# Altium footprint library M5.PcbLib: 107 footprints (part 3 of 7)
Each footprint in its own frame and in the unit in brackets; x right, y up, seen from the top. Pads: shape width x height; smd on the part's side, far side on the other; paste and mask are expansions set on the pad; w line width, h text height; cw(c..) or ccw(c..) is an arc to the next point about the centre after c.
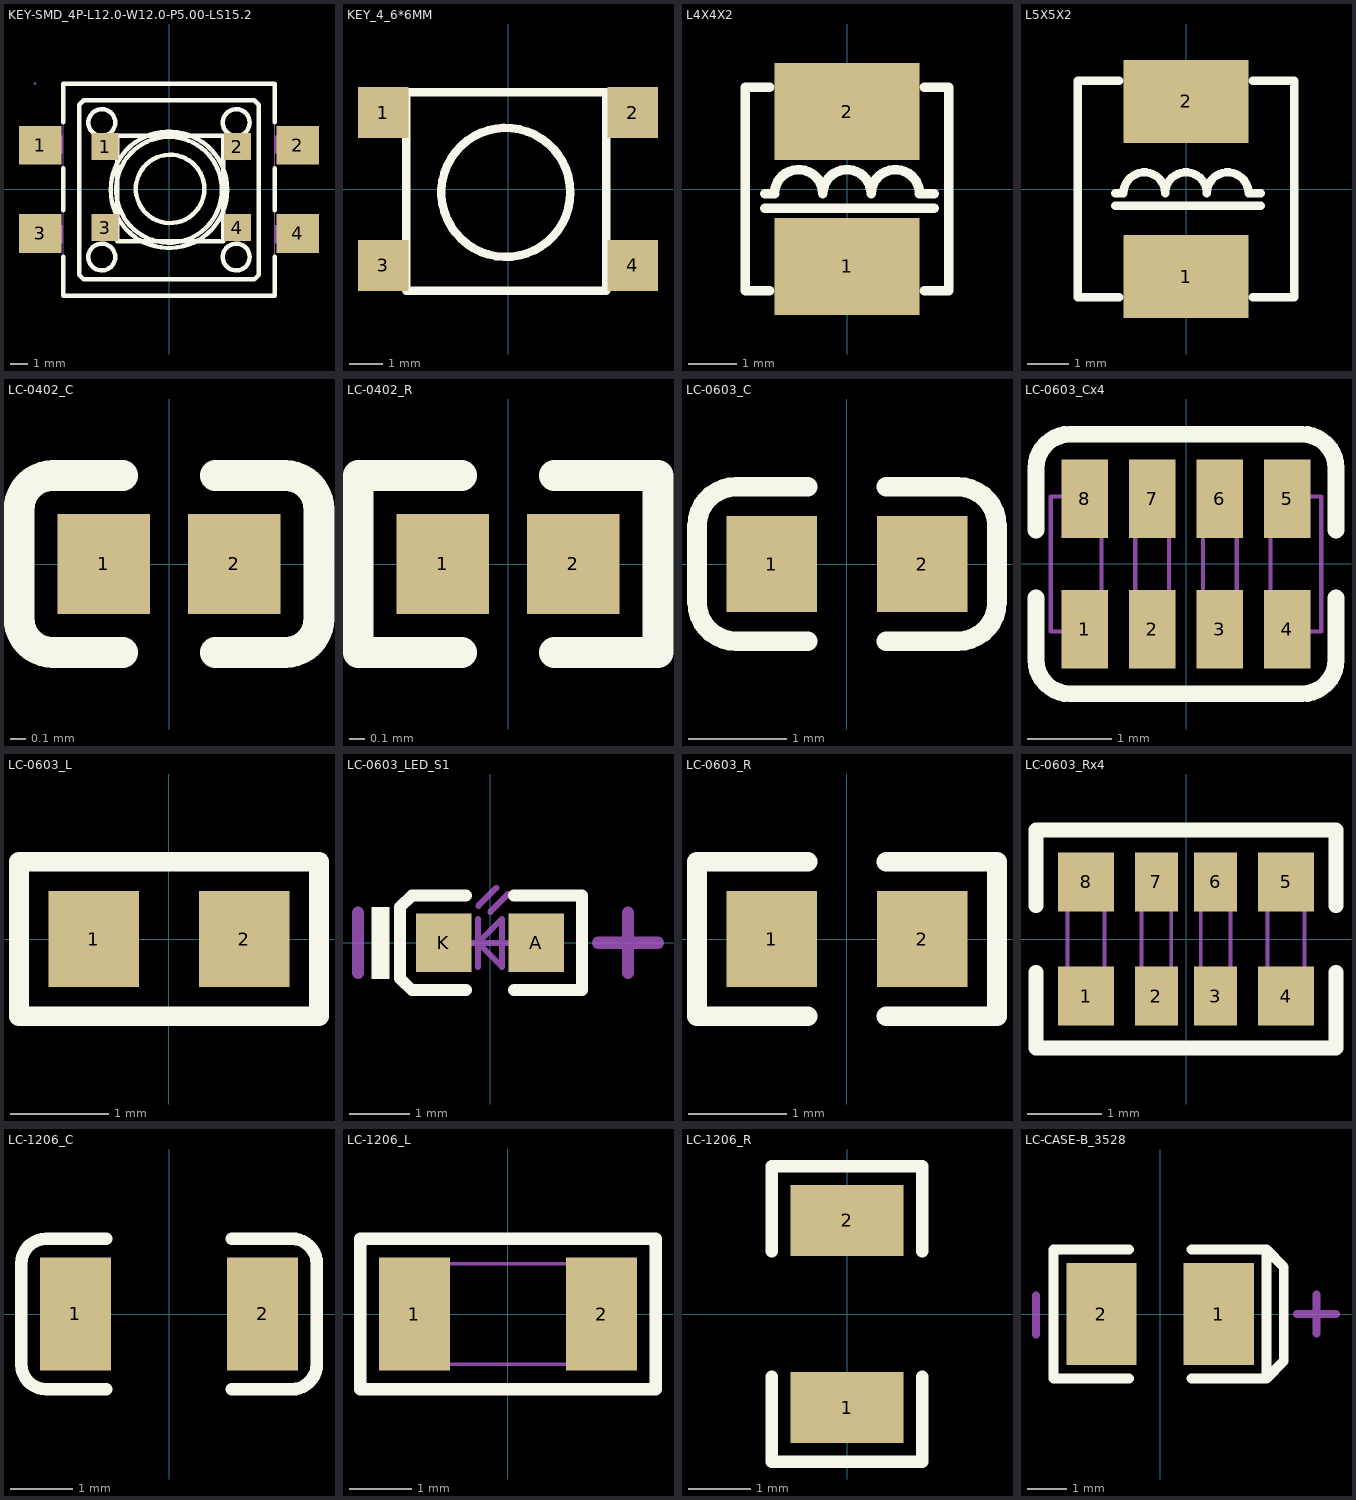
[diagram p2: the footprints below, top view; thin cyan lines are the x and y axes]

## KEY-SMD_4P-L12.0-W12.0-P5.00-LS15.2 [mil]
pads (8):
  rect 94.49x86.61 smd paste+0 mask+1.97: 1(-287.4,98.42) 2(287.4,98.42) 3(-287.4,-98.42) 4(287.4,-98.42)
  rect 60x60 smd: 1(-142.5,95.5) 2(152.5,95.5) 3(-142.5,-85.5) 4(152.5,-85.5)
Top Overlay:
  circle w10: c2.44,1.01 r76.32
  circle w10: c-150,149.03 r30
  circle w10: c150,149.03 r30
  circle w10: c-150,-150.97 r30
  circle w10: c150,-150.97 r30
  circle w10: c0,-0.97 r130
  circle w10: c0,-0.97 r118.11
  lines w10: -236.22,-149.93 -236.22,-237.19 236.22,-237.19 236.22,-149.93 ; -236.22,-46.92 -236.22,46.92 ; -236.22,149.93 -236.22,235.25 236.22,235.25 236.22,149.93 ; 236.22,-46.92 236.22,46.92 ; -200,-190.97 -190,-200.97 190,-200.97 200,-190.97 200,189.03 190,199.03 -190,199.03 -200,189.03 -200,-190.97 ; -115.22,-115.5 121,-115.5 121,119.5 -115.22,119.5 -115.22,-115.5
Mechanical 15:
  region: -296.65,236.22 -297.4,234.42 -299.21,233.67 -301.02,234.42 -301.77,236.22 -301.02,238.03 -299.21,238.78 -297.4,238.03
  region: 235.83,-119.68 235.83,-80.31 272.05,-80.31 272.05,-119.68
  region: 271.65,-119.68 271.65,-80.31 299.21,-80.31 299.21,-119.68
  region: -272.05,-119.68 -272.05,-80.31 -235.83,-80.31 -235.83,-119.68
  region: -299.21,-119.68 -299.21,-80.31 -271.65,-80.31 -271.65,-119.68
  region: 235.83,80.32 235.83,119.69 272.05,119.69 272.05,80.32
  region: 271.65,80.32 271.65,119.69 299.21,119.69 299.21,80.32
  region: -272.05,80.32 -272.05,119.69 -235.83,119.69 -235.83,80.32
  region: -299.21,80.32 -299.21,119.69 -271.65,119.69 -271.65,80.32
  lines w2: -236.22,-236.22 -236.22,236.22 236.22,236.22 236.22,-236.22 -236.22,-236.22
3D body: height 286.61, standoff -0.8, extent -164.29,-110.69 174.29,125.53
3D body: height 275.59, standoff 0, extent -420.06,-419.92 425.06,414.57

## KEY_4_6*6MM [mil]
pads (4):
  rect 60x60 smd: 1(-147.5,90.5) 2(147.5,90.5) 3(-147.5,-90.5) 4(147.5,-90.5)
Top Overlay:
  circle w10: c-2.56,-3.99 r76.32
  lines w10: -120.22,-120.5 116,-120.5 116,114.5 -120.22,114.5 -120.22,-120.5
3D body: height 286.61, standoff -0.8, extent -169.29,-115.69 169.29,120.53

## L4X4X2 [mm]
pads (2):
  rect 3x2 smd: 1(0,-1.6) 2(0,1.6)
Top Overlay:
  lines w0.2: -1.7,-0.4 1.8,-0.4 ; -1.7,-0.1 -1.5,-0.1 cw(c-1,-0.1) -0.5,-0.1 cw(c0,-0.1) 0.5,-0.1 cw(c1,-0.1) 1.5,-0.1 1.8,-0.1 ; -1.6,-2.1 -2.1,-2.1 -2.1,2.1 -1.6,2.1 ; 1.6,-2.1 2.1,-2.1 2.1,2.1 1.6,2.1
3D body: height 1.8, standoff -0.07, extent -2.03,-2.295 2.03,2.295

## L5X5X2 [mm]
pads (2):
  rect 3x2 smd: 1(0,-2.1) 2(0,2.1)
Top Overlay:
  lines w0.2: -1.7,-0.4 1.8,-0.4 ; -1.7,-0.1 -1.5,-0.1 cw(c-1,-0.1) -0.5,-0.1 cw(c0,-0.1) 0.5,-0.1 cw(c1,-0.1) 1.5,-0.1 1.8,-0.1 ; -1.6,-2.6 -2.6,-2.6 -2.6,2.6 -1.6,2.6 ; 1.6,-2.6 2.6,-2.6 2.6,2.6 1.6,2.6
3D body: height 1.9, standoff 0, extent -2.4,-2.4 2.4,2.4

## LC-0402_C [mm]
pads (2):
  rect 0.6x0.65 smd mask+0.051: 1(-0.425,0) 2(0.425,0)
Top Overlay:
  lines w0.2: -0.755,-0.575 cw(c-0.755,-0.355) -0.975,-0.355 -0.975,0.355 cw(c-0.755,0.355) -0.755,0.575 ; -0.75,-0.575 -0.3,-0.575 ; -0.75,0.575 -0.3,0.575 ; 0.3,-0.575 0.75,-0.575 ; 0.3,0.575 0.75,0.575 ; 0.755,-0.575 ccw(c0.755,-0.355) 0.975,-0.355 0.975,0.355 ccw(c0.755,0.355) 0.755,0.575
3D body: height 0.2, standoff 0, extent -0.483,-0.3 0.517,0.3

## LC-0402_R [mm]
pads (2):
  rect 0.6x0.65 smd mask+0.051: 1(-0.425,0) 2(0.425,0)
Top Overlay:
  lines w0.2: -0.3,-0.575 -0.975,-0.575 -0.975,0.575 -0.3,0.575 ; 0.3,-0.575 0.975,-0.575 0.975,0.575 0.3,0.575
3D body: height 0.41, standoff 0, extent -0.575,-0.275 0.575,0.275

## LC-0603_C [mm]
pads (2):
  rect 0.93x0.98 smd: 1(-0.77,0) 2(0.77,0)
Top Overlay:
  lines w0.2: -0.4,-0.79 -1.135,-0.79 cw(c-1.135,-0.39) -1.535,-0.39 -1.535,0.39 cw(c-1.135,0.39) -1.135,0.79 -0.4,0.79 ; 0.4,-0.79 1.135,-0.79 ccw(c1.135,-0.39) 1.535,-0.39 1.535,0.39 ccw(c1.135,0.39) 1.135,0.79 0.4,0.79
3D body: height 0.3, standoff 0, extent -0.8,-0.4 0.8,0.4

## LC-0603_Cx4 [mm]
pads (8):
  rect 0.55x0.93 smd mask+0.051: 1(-1.2,-0.77) 2(-0.4,-0.77) 3(0.4,-0.77) 4(1.2,-0.77) 5(1.2,0.77) 6(0.4,0.77) 7(-0.4,0.77) 8(-1.2,0.77)
Top Overlay:
  lines w0.2: -1.775,-0.4 -1.775,-1.135 ccw(c-1.375,-1.135) -1.375,-1.535 1.375,-1.535 ccw(c1.375,-1.135) 1.775,-1.135 1.775,-0.4 ; -1.775,0.4 -1.775,1.135 cw(c-1.375,1.135) -1.375,1.535 1.375,1.535 cw(c1.375,1.135) 1.775,1.135 1.775,0.4
Mechanical 13:
  lines w0.05: -1.6,-0.8 -1,-0.8 -1,0.8 -1.6,0.8 -1.6,-0.8 ; -0.6,-0.8 -0.2,-0.8 -0.2,0.8 -0.6,0.8 -0.6,-0.8 ; 0.2,-0.8 0.6,-0.8 0.6,0.8 0.2,0.8 0.2,-0.8 ; 1,-0.8 1.6,-0.8 1.6,0.8 1,0.8 1,-0.8

## LC-0603_L [mm]
pads (2):
  rect 0.93x0.98 smd: 1(-0.77,0) 2(0.77,0)
Top Overlay:
  lines w0.2: -1.535,-0.79 -1.535,0.79 1.535,0.79 1.535,-0.79 -1.535,-0.79
3D body: height 0.46, standoff -0.01, extent -0.824,-0.412 0.824,0.413

## LC-0603_LED_S1 [mm]
pads (2):
  rect 0.93x0.98 smd: A(0.77,0) K(-0.77,0)
Top Overlay:
  rectangle: -1.975,-0.6 -1.675,0.6
  lines w0.2: -0.4,-0.79 -1.3,-0.79 -1.5,-0.597 -1.5,0.597 -1.3,0.79 -0.4,0.79 ; 0.4,-0.79 1.535,-0.79 1.535,0.79 0.4,0.79
Mechanical 13:
  lines w0.1: -0.4,0 0.4,0 ; -0.2,-0.4 -0.2,0.4 ; -0.195,0.617 0.105,0.917 ; 0.005,0.517 0.305,0.817 ; -0.2,0 0.2,0.4 0.2,-0.4 -0.2,0
Mechanical 15:
  lines w0.203: -2.2,-0.5 -2.2,0.5 ; 1.8,0 2.8,0 ; 2.3,-0.5 2.3,0.5
3D body: height 0.6, standoff 0, extent -0.8,-0.4 0.8,0.4

## LC-0603_R [mm]
pads (2):
  rect 0.93x0.98 smd: 1(-0.77,0) 2(0.77,0)
Top Overlay:
  lines w0.2: -0.4,-0.79 -1.535,-0.79 -1.535,0.79 -0.4,0.79 ; 0.4,-0.79 1.535,-0.79 1.535,0.79 0.4,0.79
3D body: height 0.56, standoff 0, extent -0.85,-0.4 0.85,0.4

## LC-0603_Rx4 [mm]
pads (8):
  rect 0.75x0.8 smd mask+0.051: 1(-1.35,-0.77) 4(1.35,-0.77) 5(1.35,0.77) 8(-1.35,0.77)
  rect 0.58x0.8 smd mask+0.051: 2(-0.4,-0.77) 3(0.4,-0.77) 6(0.4,0.77) 7(-0.4,0.77)
Top Overlay:
  lines w0.2: -2.025,-0.45 -2.025,-1.47 2.025,-1.47 2.025,-0.45 ; -2.025,0.45 -2.025,1.47 2.025,1.47 2.025,0.45
Mechanical 13:
  lines w0.05: -1.6,-0.8 -1.1,-0.8 -1.1,0.8 -1.6,0.8 -1.6,-0.8 ; -0.6,-0.8 -0.2,-0.8 -0.2,0.8 -0.6,0.8 -0.6,-0.8 ; 0.2,-0.8 0.6,-0.8 0.6,0.8 0.2,0.8 0.2,-0.8 ; 1.1,-0.8 1.6,-0.8 1.6,0.8 1.1,0.8 1.1,-0.8
3D body: height 0.55, standoff 0, extent -1.6,-0.8 1.6,0.8

## LC-1206_C [mm]
pads (2):
  rect 1.13x1.8 smd: 1(-1.49,0) 2(1.49,0)
Top Overlay:
  lines w0.2: -1,-1.2 -1.955,-1.2 cw(c-1.955,-0.8) -2.355,-0.8 -2.355,0.8 cw(c-1.955,0.8) -1.955,1.2 -1,1.2 ; 1,-1.2 1.955,-1.2 ccw(c1.955,-0.8) 2.355,-0.8 2.355,0.8 ccw(c1.955,0.8) 1.955,1.2 1,1.2
3D body: height 1, standoff 0, extent -1.602,-0.813 1.598,0.787

## LC-1206_L [mm]
pads (2):
  rect 1.13x1.8 smd: 1(-1.49,0) 2(1.49,0)
Top Overlay:
  lines w0.2: -2.355,-1.2 -2.355,1.2 2.355,1.2 2.355,-1.2 -2.355,-1.2
Mechanical 13:
  lines w0.05: -1.6,-0.8 -1.6,0.8 1.6,0.8 1.6,-0.8 -1.6,-0.8

## LC-1206_R [mm]
pads (2):
  rect 1.8x1.13 smd: 1(0,-1.49) 2(0,1.49)
Top Overlay:
  lines w0.2: -1.2,-1 -1.2,-2.355 1.2,-2.355 1.2,-1 ; -1.2,1 -1.2,2.355 1.2,2.355 1.2,1
3D body: height 0.85, standoff 0, extent -0.866,-1.7 0.864,1.65

## LC-CASE-B_3528 [mm]
pads (2):
  rect 1.8x2.6 smd: 1(1.5,0) 2(-1.5,0)
Top Overlay:
  lines w0.254: -0.8,-1.65 -2.727,-1.65 -2.727,1.65 -0.8,1.65 ; 0.8,-1.65 2.727,-1.65 ; 0.8,1.65 2.727,1.65 ; 2.727,-1.65 3.163,-1.2 3.163,1.2 2.727,1.65 ; 2.727,-1.65 2.727,1.65
Mechanical 15:
  lines w0.203: -3.175,-0.525 -3.175,0.475 ; 3.5,0 4.5,0 ; 4,-0.5 4,0.5
3D body: height 2.03, standoff 0, extent -1.85,-1.465 1.85,1.465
